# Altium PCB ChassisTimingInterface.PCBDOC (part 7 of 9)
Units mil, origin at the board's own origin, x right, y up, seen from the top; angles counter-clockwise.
Board outline 7007.87 x 4368.85 mil, 10 copper layers (Top Layer, Int1 (GND), Int2 (Sign), Int3 (Sign), Int4 (PWR), Int5 (GND), Int6 (Sign), Int7 (Sign), Int8 (GND), Bottom Layer), stack 54.89 mil thick; 537 components, 525 nets, 2288 pads, 1306 vias.
Unrouted connection lines stored in the file: 373.
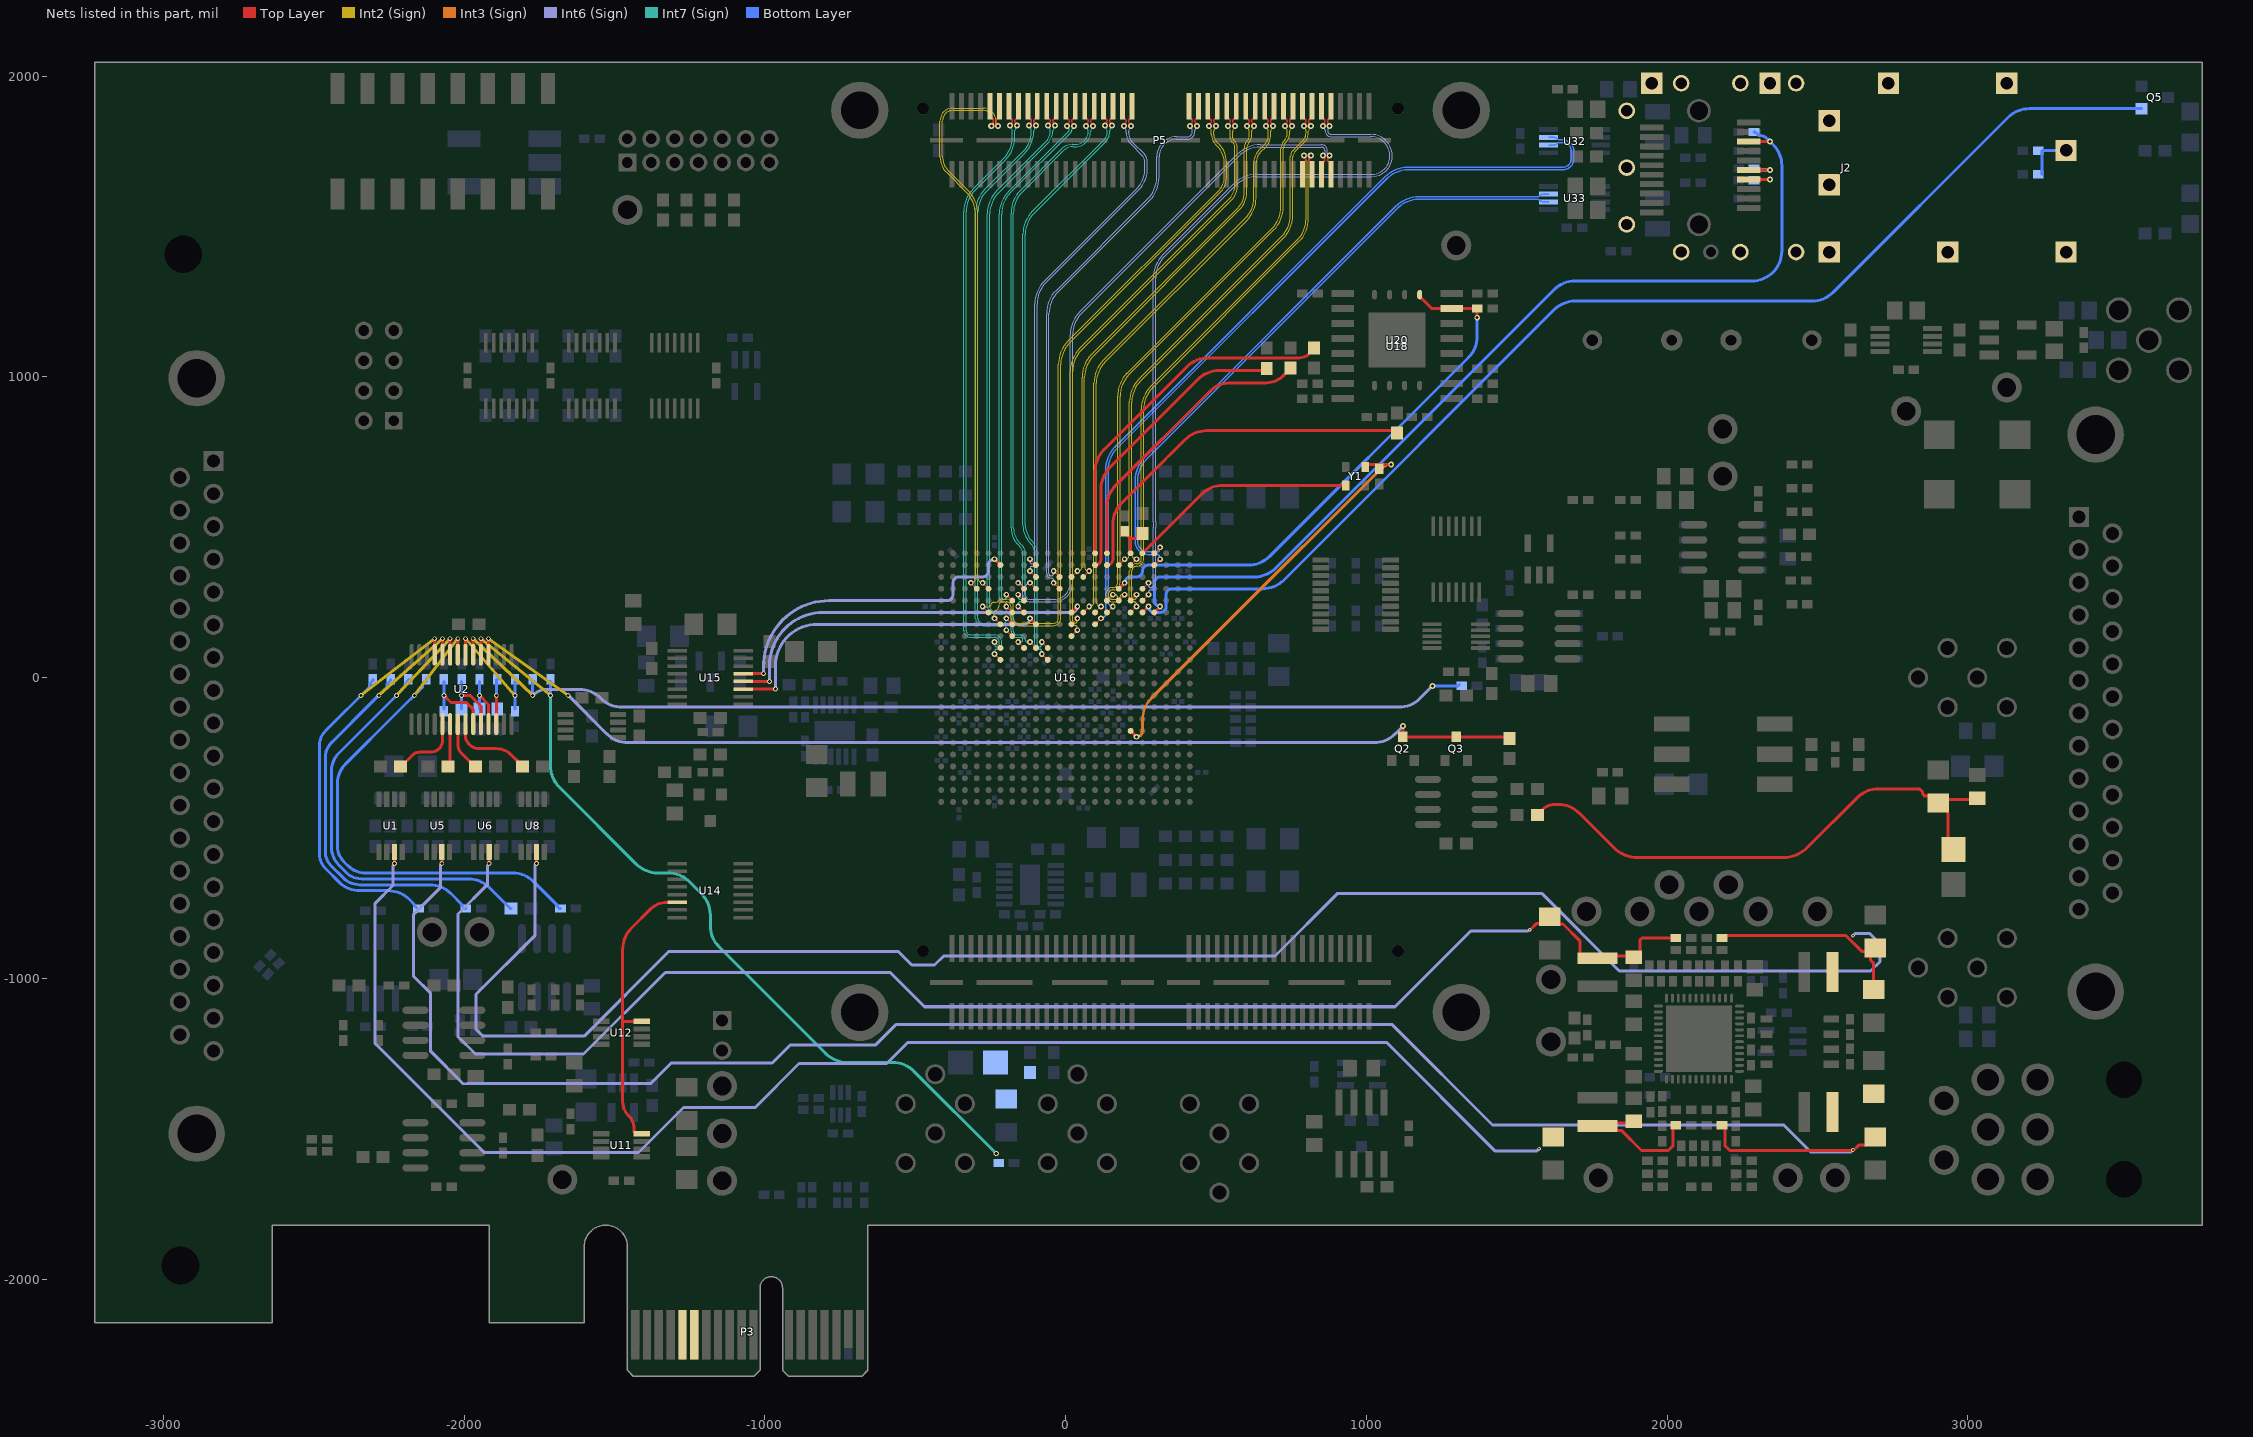
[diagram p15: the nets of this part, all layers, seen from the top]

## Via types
v1: diameter 19, hole 10, Top Layer to Bottom Layer, tented both sides, 667 vias
v2: diameter 20, hole 10, Top Layer to Bottom Layer, tented both sides, 248 vias
v3: diameter 16, hole 10, Top Layer to Bottom Layer, tented both sides, 191 vias
v4: diameter 12, hole 6, Top Layer to Bottom Layer, tented both sides, 85 vias
v5: diameter 19.68, hole 10, Top Layer to Bottom Layer, tented both sides, 50 vias
v6: diameter 17.72, hole 10, Top Layer to Bottom Layer, tented both sides, 19 vias
v7: diameter 19, hole 10, Top Layer to Bottom Layer, 15 vias
v8: diameter 23.62, hole 10, Top Layer to Bottom Layer, tented both sides, 14 vias
v9: diameter 20, hole 10, Top Layer to Bottom Layer, 11 vias
v10: diameter 16, hole 10, Top Layer to Bottom Layer, 3 vias
v11: diameter 22, hole 12, Top Layer to Bottom Layer, tented both sides, 2 vias
v12: diameter 19.02, hole 10, Top Layer to Bottom Layer, tented both sides, 1 vias

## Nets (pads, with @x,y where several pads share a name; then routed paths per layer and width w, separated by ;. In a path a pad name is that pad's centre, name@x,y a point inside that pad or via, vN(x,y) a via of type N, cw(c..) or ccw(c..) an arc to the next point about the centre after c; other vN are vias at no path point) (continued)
S33_48.S47_N: P5.67 U16.U18 | length 1841.6
  Top Layer w5: U16.U18@216.54,255.91 v1(236.22,275.59) ; v2(815.43,1736.22) cw(c807.53,1736.22) 813.12,1730.63 810.97,1728.48 ccw(c817.59,1721.87) 808.23,1721.87 ccw(c815.64,1721.87) 810.4,1716.63 ccw(c812.94,1719.18) 812.94,1715.58 cw(c812.94,1711.99) 815.48,1714.53 817.06,1712.95 cw(c810.72,1706.62) 819.68,1706.62 P5.67@819.68,1673.83
  Int2 (Sign) w3: v1(236.22,275.59) 236.22,267.78 cw(c228.35,267.78) 228.35,259.91 cw(c228.35,267.78) 220.47,267.78 220.47,354.33 cw(c236.22,354.33) 236.22,370.08 236.35,370.08 ccw(c236.35,393.7) 259.97,393.7 259.97,892.27 cw(c359.97,892.27) 289.13,962.86 cw(c359.97,892.27) 289.26,962.98 776.33,1450.05 ccw(c700.03,1526.35) 807.93,1526.35 807.93,1718.11 cw(c826.88,1718.11) 813.48,1731.51 ccw(c808.77,1736.22) v2(815.43,1736.22)
S33_48.S47_P: P5.65 U16.U17 | length 1854.2
  Top Layer w5: U16.U17@216.54,216.54 v1(236.22,236.22) ; P5.65@788.18,1673.83 788.18,1706.62 cw(c797.14,1706.62) 790.81,1712.96 792.38,1714.53 cw(c794.92,1711.99) 794.92,1715.58 ccw(c794.92,1719.18) 797.46,1716.63 ccw(c792.23,1721.87) 799.63,1721.87 ccw(c790.27,1721.87) 796.9,1728.48 794.74,1730.64 cw(c800.33,1736.22) v2(792.43,1736.22)
  Int2 (Sign) w3: v1(236.22,236.22) 236.22,244.03 ccw(c228.35,244.03) 228.35,251.91 cw(c228.35,267.78) 212.47,267.78 212.47,354.33 cw(c236.22,354.33) 236.22,378.08 236.35,378.08 ccw(c236.35,393.7) 251.97,393.7 251.97,893 cw(c358.22,893) 283.09,968.13 770.64,1455.68 ccw(c699.93,1526.39) 799.93,1526.39 799.93,1718.11 ccw(c780.98,1718.11) 794.38,1731.51 cw(c799.09,1736.22) v2(792.43,1736.22)
S33_48.S48_N: P5.69 U16.H19 | length 2326.4
  Top Layer w5: v1(-157.48,314.96) U16.H19@-137.8,295.28 ; P5.69@851.16,1673.83 851.16,1706.62 cw(c860.13,1706.62) 853.79,1712.96 855.37,1714.53 cw(c857.9,1711.99) 857.9,1715.58 ccw(c857.9,1719.18) 860.45,1716.63 ccw(c855.21,1721.87) 862.61,1721.87 ccw(c853.25,1721.87) 859.88,1728.48 857.72,1730.64 cw(c863.31,1736.22) v2(855.41,1736.22)
  Int6 (Sign) w3: v1(-157.48,314.96) cw(c-157.48,299.28) -141.8,299.28 -141.8,275.53 ccw(c-118.11,275.53) -118.11,251.84 -39.37,251.84 ccw(c-39.37,314.96) 23.75,314.96 23.75,1139.81 cw(c123.75,1139.81) 53.04,1210.52 577.01,1734.49 cw(c647.72,1663.78) 647.72,1763.78 851.1,1763.78 cw(c851.1,1751.97) 862.91,1751.97 862.91,1743.72 cw(c855.41,1743.72) v2(855.41,1736.22)
S33_48.S48_P: P5.71 U16.J19 | length 2326.4
  Top Layer w5: v1(-118.11,314.96) U16.J19@-98.43,295.28 ; v2(878.41,1736.22) cw(c870.52,1736.22) 876.1,1730.63 873.95,1728.48 ccw(c880.58,1721.87) 871.21,1721.87 ccw(c878.62,1721.87) 873.38,1716.63 ccw(c875.93,1719.18) 875.93,1715.58 cw(c875.93,1711.99) 878.46,1714.53 880.05,1712.95 cw(c873.7,1706.62) 882.66,1706.62 P5.71@882.66,1673.83
  Int6 (Sign) w3: v1(-118.11,314.96) ccw(c-118.11,299.28) -133.8,299.28 -133.8,275.53 ccw(c-118.11,275.53) -118.11,259.84 -39.37,259.84 ccw(c-39.37,314.96) 15.75,314.96 15.75,1139.85 cw(c123.65,1139.85) 47.35,1216.15 571.38,1740.18 cw(c647.68,1663.88) 647.68,1771.78 851.1,1771.78 cw(c851.1,1751.97) 870.91,1751.97 870.91,1743.72 ccw(c878.41,1743.72) v2(878.41,1736.22)
S49_64.S49_N: P5.12 U16.D19 | length 1942
  Top Layer w5: v1(-314.96,314.96) U16.D19@-295.28,295.28 ; v2(-223.92,1834.65) ccw(c-231.82,1834.65) -226.22,1840.22 -227.52,1841.52 cw(c-218.83,1850.21) -231.12,1850.21 -231.12,1851.36 cw(c-223.71,1851.36) -228.95,1856.59 cw(c-226.41,1854.05) -226.41,1857.65 ccw(c-226.41,1861.24) -223.87,1858.69 -222.29,1860.27 ccw(c-228.63,1866.61) -219.67,1866.61 P5.12@-219.67,1899.4
  Int2 (Sign) w3: v1(-314.96,314.96) ccw(c-314.96,330.65) -299.28,330.65 -299.28,1541.82 ccw(c-399.28,1541.82) -328.57,1612.53 -395.65,1679.61 cw(c-343.01,1732.24) -417.45,1732.24 -417.45,1850.39 cw(c-374.02,1850.39) -374.02,1893.83 -274.06,1893.83 cw(c-274.06,1851.18) -231.42,1851.18 -231.42,1842.15 ccw(c-223.92,1842.15) v2(-223.92,1834.65)
S49_64.S49_P: P5.10 U16.E19 | length 1916.9
  Top Layer w5: v1(-275.59,314.96) U16.E19@-255.91,295.28 ; P5.10@-251.17,1899.4 -251.17,1866.61 ccw(c-242.21,1866.61) -248.55,1860.28 -246.97,1858.7 ccw(c-244.43,1861.24) -244.43,1857.65 cw(c-244.43,1854.05) -241.89,1856.59 cw(c-247.12,1851.36) -239.72,1851.36 -239.72,1850.21 cw(c-252.01,1850.21) -243.32,1841.52 -244.6,1840.23 ccw(c-239.02,1834.65) v2(-246.92,1834.65)
  Int2 (Sign) w3: v1(-275.59,314.96) cw(c-275.59,330.65) -291.28,330.65 -291.28,1541.92 ccw(c-399.04,1541.92) -322.84,1618.11 -389.96,1685.24 cw(c-342.92,1732.28) -409.45,1732.28 -409.45,1850.39 cw(c-374.02,1850.39) -374.02,1885.83 -274.06,1885.83 cw(c-274.06,1851.18) -239.42,1851.18 -239.42,1842.15 cw(c-246.92,1842.15) v2(-246.92,1834.65)
S49_64.S50_N: P5.14 U16.F14 | length 2018.6
  Top Layer w5: v1(-236.22,118.11) U16.F14@-216.54,98.43 ; P5.14@-188.19,1899.4 -188.19,1866.61 ccw(c-179.22,1866.61) -185.57,1860.28 -183.99,1858.7 ccw(c-181.45,1861.24) -181.45,1857.65 cw(c-181.45,1854.05) -178.9,1856.59 cw(c-184.14,1851.36) -176.74,1851.36 cw(c-189.01,1851.36) -180.33,1842.68 -181.62,1841.39 ccw(c-176.04,1835.8) v2(-183.94,1835.8)
  Int7 (Sign) w3: v1(-236.22,118.11) -236.22,110.3 ccw(c-228.35,110.3) -228.35,102.43 ccw(c-228.35,110.3) -220.47,110.3 -220.47,118.11 ccw(c-236.22,118.11) -236.22,133.86 -314.96,133.86 cw(c-314.96,157.61) -338.71,157.61 -338.71,196.98 -338.71,1548.37 cw(c-230.81,1548.37) -307.11,1624.67 -205.72,1726.05 ccw(c-276.44,1796.76) -176.44,1796.76 -176.44,1817.7 ccw(c-195.38,1817.7) -181.99,1831.09 cw(c-177.28,1835.8) v2(-183.94,1835.8)
S49_64.S50_P: P5.16 U16.F13 | length 2031.2
  Top Layer w5: v1(-236.22,78.74) U16.F13@-216.54,59.06 ; v2(-160.94,1835.8) ccw(c-168.83,1835.8) -163.24,1841.38 -164.54,1842.68 cw(c-155.86,1851.36) -168.14,1851.36 cw(c-160.73,1851.36) -165.97,1856.59 cw(c-163.42,1854.05) -163.42,1857.65 ccw(c-163.42,1861.24) -160.89,1858.69 -159.31,1860.27 ccw(c-165.65,1866.61) -156.68,1866.61 P5.16@-156.69,1899.4
  Int7 (Sign) w3: v1(-236.22,78.74) -236.22,86.55 cw(c-228.35,86.55) -228.35,94.43 ccw(c-228.35,110.3) -212.47,110.3 -212.47,118.11 ccw(c-236.22,118.11) -236.22,141.86 -314.96,141.86 cw(c-314.96,157.61) -330.71,157.61 -330.71,1460.63 -330.71,1548.33 cw(c-230.71,1548.33) -301.42,1619.04 -200.04,1720.42 ccw(c-276.34,1796.72) -168.44,1796.72 -168.44,1817.7 cw(c-149.49,1817.7) -162.88,1831.09 ccw(c-167.59,1835.8) v2(-160.94,1835.8)
S49_64.S51_N: P5.20 U16.G16 | length 1924
  Top Layer w5: v1(-196.85,196.85) U16.G16@-177.17,177.17 ; v2(-97.94,1834.95) ccw(c-105.83,1834.95) -100.24,1840.53 -101.54,1841.82 cw(c-92.84,1850.51) -105.14,1850.51 -105.14,1851.36 cw(c-97.73,1851.36) -102.97,1856.59 cw(c-100.42,1854.05) -100.42,1857.65 ccw(c-100.42,1861.24) -97.89,1858.69 -96.31,1860.27 ccw(c-102.65,1866.61) -93.68,1866.61 P5.20@-93.69,1899.4
  Int7 (Sign) w3: v1(-196.85,196.85) -196.85,189.04 cw(c-204.72,189.04) -204.72,181.17 -275.59,181.17 cw(c-275.59,196.91) -291.34,196.91 -291.34,1546.82 cw(c-191.34,1546.82) -262.05,1617.53 -135.52,1744.06 ccw(c-208.15,1816.69) -105.44,1816.69 -105.44,1816.84 cw(c-86.49,1816.84) -99.88,1830.24 ccw(c-104.59,1834.95) v2(-97.94,1834.95)
S49_64.S51_P: P5.18 U16.G15 | length 1936.5
  Top Layer w5: v1(-196.85,157.48) U16.G15@-177.17,137.8 ; P5.18@-125.19,1899.4 -125.19,1866.61 ccw(c-116.22,1866.61) -122.57,1860.28 -120.99,1858.7 ccw(c-118.45,1861.24) -118.45,1857.65 cw(c-118.45,1854.05) -115.9,1856.59 cw(c-121.14,1851.36) -113.74,1851.36 -113.74,1850.51 cw(c-126.03,1850.51) -117.34,1841.82 -118.62,1840.53 ccw(c-113.04,1834.95) v2(-120.94,1834.95)
  Int7 (Sign) w3: v1(-196.85,157.48) -196.85,165.29 ccw(c-204.72,165.29) -204.72,173.17 -275.59,173.17 cw(c-275.59,196.91) -299.34,196.91 -299.34,1546.86 cw(c-191.44,1546.86) -267.74,1623.16 -141.29,1749.6 ccw(c-208.52,1816.84) -113.44,1816.84 ccw(c-132.38,1816.84) -118.99,1830.24 cw(c-114.28,1834.95) v2(-120.94,1834.95)
S49_64.S52_N: P5.22 U16.H14 | length 2000.4
  Top Layer w5: v1(-157.48,118.11) U16.H14@-137.8,98.43 ; P5.22@-62.2,1899.4 -62.2,1866.61 ccw(c-53.24,1866.61) -59.58,1860.28 -58,1858.7 ccw(c-55.46,1861.24) -55.46,1857.65 cw(c-55.46,1854.05) -52.92,1856.59 cw(c-58.16,1851.36) -50.75,1851.36 -50.75,1850.51 cw(c-63.04,1850.51) -54.35,1841.82 -55.64,1840.53 ccw(c-50.05,1834.95) v2(-57.95,1834.95)
  Int7 (Sign) w3: v1(-157.48,118.11) -149.67,118.11 ccw(c-149.67,125.98) -141.8,125.98 ccw(c-149.67,125.98) -149.67,133.86 -161.42,133.86 cw(c-161.42,153.67) -181.23,153.67 -181.23,196.98 ccw(c-196.85,196.98) -196.85,212.6 -236.22,212.6 cw(c-236.22,236.35) -259.97,236.35 -259.97,1542.18 cw(c-152.07,1542.18) -228.37,1618.48 -64.91,1781.93 ccw(c-99.82,1816.84) -50.45,1816.84 ccw(c-69.4,1816.84) -56,1830.24 cw(c-51.29,1834.95) v2(-57.95,1834.95)
S49_64.S52_P: P5.24 U16.J14 | length 2000.5
  Top Layer w5: v1(-118.11,118.11) U16.J14@-98.43,98.43 ; v2(-34.95,1834.95) ccw(c-42.85,1834.95) -37.26,1840.53 -38.55,1841.82 cw(c-29.86,1850.51) -42.15,1850.51 -42.15,1851.36 cw(c-34.75,1851.36) -39.98,1856.59 cw(c-37.44,1854.05) -37.44,1857.65 ccw(c-37.44,1861.24) -34.91,1858.69 -33.33,1860.27 ccw(c-39.66,1866.61) -30.7,1866.61 P5.24@-30.7,1899.4
  Int7 (Sign) w3: v1(-118.11,118.11) -125.92,118.11 cw(c-125.92,125.98) -133.8,125.98 ccw(c-149.67,125.98) -149.67,141.86 -161.42,141.86 cw(c-161.42,153.67) -173.23,153.67 -173.23,196.98 ccw(c-196.85,196.98) -196.85,220.6 -236.22,220.6 cw(c-236.22,236.35) -251.97,236.35 -251.97,1542.14 cw(c-151.97,1542.14) -222.68,1612.85 -59.25,1776.28 ccw(c-99.8,1816.83) -42.45,1816.83 cw(c-23.5,1816.84) -36.9,1830.24 ccw(c-41.61,1834.95) v2(-34.95,1834.95)
S49_64.S53_N: P5.28 U16.G18 | length 1793.8
  Top Layer w5: v1(-196.85,275.59) U16.G18@-177.17,255.91 ; v2(28.05,1834.65) ccw(c20.15,1834.65) 25.74,1840.22 24.45,1841.52 cw(c33.14,1850.21) 20.85,1850.21 20.85,1851.36 cw(c28.25,1851.36) 23.02,1856.59 cw(c25.56,1854.05) 25.56,1857.65 ccw(c25.56,1861.24) 28.09,1858.69 29.67,1860.27 ccw(c23.34,1866.61) 32.3,1866.61 P5.28@32.3,1899.4
  Int7 (Sign) w3: v1(-196.85,275.59) -196.85,267.78 cw(c-204.72,267.78) -204.72,259.91 cw(c-204.72,267.78) -212.6,267.78 -212.6,1540.98 cw(c-112.6,1540.98) -183.31,1611.69 17.42,1812.42 ccw(c9.87,1819.97) 20.55,1819.97 cw(c31.22,1819.97) 23.67,1827.52 26.1,1829.94 ccw(c21.39,1834.65) v2(28.05,1834.65)
S49_64.S53_P: P5.26 U16.G17 | length 1806.3
  Top Layer w5: v1(-196.85,236.22) U16.G17@-177.17,216.54 ; P5.26@0.8,1899.4 0.8,1866.61 ccw(c9.76,1866.61) 3.42,1860.28 5,1858.7 ccw(c7.54,1861.24) 7.54,1857.65 cw(c7.54,1854.05) 10.08,1856.59 cw(c4.84,1851.36) 12.25,1851.36 12.25,1850.21 cw(c-0.04,1850.21) 8.65,1841.52 7.36,1840.23 ccw(c12.95,1834.65) v2(5.05,1834.65)
  Int7 (Sign) w3: v1(-196.85,236.22) -196.85,244.03 ccw(c-204.72,244.03) -204.72,251.91 cw(c-204.72,267.78) -220.6,267.78 -220.6,1541.02 cw(c-112.7,1541.02) -189,1617.31 10.59,1816.9 ccw(c5.87,1821.62) 12.55,1821.62 ccw(c5.87,1821.62) 10.59,1826.34 7,1829.94 cw(c11.71,1834.65) v2(5.05,1834.65)
S49_64.S54_N: P5.30 U16.H18 | length 1836.4
  Top Layer w5: v1(-157.48,275.59) U16.H18@-137.8,255.91 ; P5.30@63.78,1899.4 63.78,1866.61 ccw(c72.74,1866.61) 66.4,1860.28 67.98,1858.7 ccw(c70.52,1861.24) 70.52,1857.65 cw(c70.52,1854.05) 73.06,1856.59 cw(c67.83,1851.36) 75.23,1851.36 75.23,1850.21 cw(c62.94,1850.21) 71.63,1841.52 70.35,1840.23 ccw(c75.93,1834.65) v2(68.03,1834.65)
  Int7 (Sign) w3: v1(-157.48,275.59) -157.48,267.78 ccw(c-149.67,267.75) -141.86,267.78 -141.86,413.28 ccw(c-170.93,413.28) -150.37,433.84 -157.52,440.99 cw(c-100.3,498.21) -181.23,498.21 -181.23,1543.73 cw(c-73.33,1543.73) -149.62,1620.03 -10.03,1759.63 cw(c22.3,1727.31) 22.3,1773.02 32.01,1773.02 ccw(c32.01,1816.54) 75.53,1816.54 ccw(c56.58,1816.54) 69.98,1829.94 cw(c74.69,1834.65) v2(68.03,1834.65)
S49_64.S54_P: P5.32 U16.H17 | length 1848.7
  Top Layer w5: v1(-157.48,236.22) U16.H17@-137.8,216.54 ; v2(91.03,1834.65) ccw(c83.13,1834.65) 88.73,1840.22 87.43,1841.52 cw(c96.12,1850.21) 83.83,1850.21 83.83,1851.36 cw(c91.24,1851.36) 86,1856.59 cw(c88.54,1854.05) 88.54,1857.65 ccw(c88.54,1861.24) 91.08,1858.69 92.66,1860.27 ccw(c86.32,1866.61) 95.28,1866.61 P5.32@95.28,1899.4
  Int7 (Sign) w3: v1(-157.48,236.22) -157.48,244.03 cw(c-149.61,244.03) -149.61,251.91 ccw(c-149.61,267.65) -133.86,267.65 -133.86,413.39 ccw(c-170.68,413.39) -144.64,439.42 -151.82,446.6 cw(c-100.15,498.28) -173.23,498.28 -173.23,1543.69 cw(c-73.23,1543.69) -143.94,1614.4 -6.71,1751.63 cw(c25.61,1719.31) 25.61,1765.02 32.01,1765.02 ccw(c32.01,1816.54) 83.53,1816.5 ; 83.53,1816.54 cw(c102.48,1816.54) 89.08,1829.94 ccw(c84.37,1834.65) v2(91.03,1834.65)
S49_64.S55_N: P5.36 U16.K14 | length 1980
  Top Layer w5: v1(-78.74,118.11) U16.K14@-59.06,98.43 ; v2(154.03,1834.95) ccw(c146.13,1834.95) 151.73,1840.53 150.43,1841.82 cw(c159.12,1850.51) 146.83,1850.51 146.83,1851.36 cw(c154.24,1851.36) 149,1856.59 cw(c151.54,1854.05) 151.54,1857.65 ccw(c151.54,1861.24) 154.08,1858.69 155.66,1860.27 ccw(c149.32,1866.61) 158.28,1866.61 P5.36@158.28,1899.4
  Int7 (Sign) w3: v1(-78.74,118.11) -78.74,110.3 cw(c-86.61,110.3) -86.61,102.43 cw(c-86.61,110.3) -94.49,110.3 -94.49,413.48 ccw(c-150.08,413.48) -110.77,452.79 cw(c-55.03,508.53) -133.86,508.53 -133.86,1473.77 cw(c-33.86,1473.77) -104.57,1544.48 136.32,1785.37 ccw(c111.67,1810.02) 146.53,1810.02 146.53,1816.84 cw(c165.48,1816.84) 152.08,1830.24 ccw(c147.37,1834.95) v2(154.03,1834.95)
S49_64.S55_P: P5.34 U16.K13 | length 1992.7
  Top Layer w5: v1(-78.74,78.74) U16.K13@-59.06,59.06 ; P5.34@126.78,1899.4 126.78,1866.61 ccw(c135.74,1866.61) 129.4,1860.28 130.98,1858.7 ccw(c133.52,1861.24) 133.52,1857.65 cw(c133.52,1854.05) 136.06,1856.59 cw(c130.83,1851.36) 138.23,1851.36 138.23,1850.51 cw(c125.94,1850.51) 134.63,1841.82 133.35,1840.53 ccw(c138.93,1834.95) v2(131.03,1834.95)
  Int7 (Sign) w3: v1(-78.74,78.74) -78.74,86.55 ccw(c-86.61,86.55) -86.61,94.43 cw(c-86.61,110.3) -102.49,110.3 -102.49,413.39 ccw(c-150.32,413.39) -116.5,447.21 -118.11,448.82 cw(c-60.78,506.15) -141.86,506.15 -141.86,1473.81 cw(c-33.96,1473.81) -110.25,1550.11 129.95,1790.32 ccw(c109.25,1811.02) 138.53,1811.02 138.53,1816.84 ccw(c119.58,1816.84) 132.98,1830.24 cw(c137.69,1834.95) v2(131.03,1834.95)
S49_64.S56_N: P5.38 U16.J21 | length 1749.2
  Top Layer w5: v1(-118.11,393.7) U16.J21@-98.43,374.02 ; P5.38@189.76,1899.4 189.76,1866.61 ccw(c198.73,1866.61) 192.38,1860.28 193.96,1858.7 ccw(c196.5,1861.24) 196.5,1857.65 cw(c196.5,1854.05) 199.05,1856.59 cw(c193.81,1851.36) 201.21,1851.36 201.21,1850.21 cw(c188.92,1850.21) 197.61,1841.52 196.33,1840.23 ccw(c201.91,1834.65) v2(194.01,1834.65)
  Int6 (Sign) w3: v1(-118.11,393.7) -118.11,385.89 ccw(c-110.24,385.89) -110.24,378.02 ccw(c-110.24,385.89) -102.36,385.89 -102.36,1242.21 cw(c5.54,1242.21) -70.79,1318.47 ; -70.76,1318.51 238.37,1627.64 ccw(c177.04,1688.98) 263.78,1688.98 263.78,1716.54 ccw(c237.11,1716.54) 255.97,1735.39 216.88,1774.48 cw(c253.97,1811.57) 201.51,1811.57 201.51,1816.54 ccw(c182.57,1816.54) 195.96,1829.94 cw(c200.67,1834.65) v2(194.01,1834.65)
S49_64.S56_P: P5.40 U16.J20 | length 1761.8
  Top Layer w5: v1(-118.11,354.33) U16.J20@-98.43,334.65 ; v2(217.01,1834.65) ccw(c209.12,1834.65) 214.71,1840.22 213.41,1841.52 cw(c222.11,1850.21) 209.81,1850.21 209.81,1851.36 cw(c217.22,1851.36) 211.98,1856.59 cw(c214.53,1854.05) 214.53,1857.65 ccw(c214.53,1861.24) 217.06,1858.69 218.64,1860.27 ccw(c212.3,1866.61) 221.27,1866.61 P5.40@221.26,1899.4
  Int6 (Sign) w3: v1(-118.11,354.33) -118.11,362.14 cw(c-110.24,362.14) -110.24,370.02 ccw(c-110.24,385.89) -94.36,385.89 -94.36,1242.17 cw(c5.64,1242.17) -65.07,1312.88 244.13,1622.09 ccw(c177.39,1688.83) 271.78,1688.83 271.78,1716.6 ccw(c237.28,1716.6) 261.67,1741 224.26,1778.42 ; v2(217.01,1834.65) cw(c210.36,1834.65) 215.07,1829.94 ccw(c228.46,1816.54) 209.52,1816.54 209.51,1811.61 ccw(c254.05,1811.61) 222.56,1780.12 224.24,1778.44
S49_64.S57_N: P5.44 U16.L20 | length 1848.9
  Top Layer w5: v1(-39.37,354.33) U16.L20@-19.69,334.65 ; v2(437.48,1834.65) ccw(c429.58,1834.65) 435.18,1840.22 433.88,1841.52 cw(c442.57,1850.21) 430.28,1850.21 430.28,1851.36 cw(c437.69,1851.36) 432.45,1856.59 cw(c434.99,1854.05) 434.99,1857.65 ccw(c434.99,1861.24) 437.53,1858.69 439.11,1860.27 ccw(c432.77,1866.61) 441.73,1866.61 P5.44@441.73,1899.4
  Int6 (Sign) w3: v1(-39.37,354.33) -39.37,346.52 cw(c-47.24,346.52) -47.24,338.65 cw(c-47.24,346.52) -55.12,346.52 -55.12,1210.55 cw(c44.88,1210.55) -25.83,1281.26 279.44,1586.53 ccw(c203.14,1662.82) 311.04,1662.82 311.04,1731.24 cw(c370.08,1731.24) 370.08,1790.28 405.3,1790.28 ccw(c405.3,1814.96) 429.98,1814.96 429.98,1818.9 cw(c443.24,1818.9) 433.86,1828.26 435.53,1829.94 ccw(c430.82,1834.65) v2(437.48,1834.65)
S49_64.S57_P: P5.42 U16.L19 | length 1861.4
  Top Layer w5: v1(-39.37,314.96) U16.L19@-19.69,295.28 ; P5.42@410.23,1899.4 410.23,1866.61 ccw(c419.19,1866.61) 412.85,1860.28 414.43,1858.7 ccw(c416.97,1861.24) 416.97,1857.65 cw(c416.97,1854.05) 419.51,1856.59 cw(c414.28,1851.36) 421.68,1851.36 421.68,1850.21 cw(c409.39,1850.21) 418.08,1841.52 416.8,1840.23 ccw(c422.38,1834.65) v2(414.48,1834.65)
  Int6 (Sign) w3: v1(-39.37,314.96) -39.37,322.77 ccw(c-47.24,322.77) -47.24,330.65 cw(c-47.24,346.52) -63.12,346.52 -63.12,1210.59 cw(c44.78,1210.59) -31.55,1286.85 ; -31.51,1286.89 273.75,1592.15 ccw(c203.04,1662.86) 303.04,1662.86 303.04,1731.24 cw(c370.08,1731.24) 370.08,1798.28 405.3,1798.28 ccw(c405.3,1814.96) 421.98,1814.96 421.98,1818.9 ccw(c408.73,1818.9) 418.11,1828.26 416.42,1829.95 cw(c421.14,1834.65) v2(414.48,1834.65)
S49_64.S58_N: P5.46 U16.E17 | length 2306
  Top Layer w5: v1(-275.59,236.22) U16.E17@-255.91,216.54 ; P5.46@473.21,1899.4 473.21,1866.61 ccw(c482.18,1866.61) 475.83,1860.28 477.41,1858.7 ccw(c479.95,1861.24) 479.95,1857.65 cw(c479.95,1854.05) 482.5,1856.59 cw(c477.26,1851.36) 484.66,1851.36 484.66,1850.21 cw(c472.37,1850.21) 481.06,1841.52 479.78,1840.23 ccw(c485.36,1834.65) v2(477.46,1834.65)
  Int2 (Sign) w3: v1(-275.59,236.22) -252.95,236.22 ccw(c-252.95,239.22) -250,238.69 cw(c-236.22,236.22) -236.22,250.22 ccw(c-236.22,270.44) -221.92,256.14 cw(c-212.68,246.91) -212.68,259.97 -196.85,259.97 cw(c-196.85,236.35) -173.23,236.35 -173.23,196.85 ccw(c-157.48,196.85) -157.48,181.1 -39.37,181.1 ccw(c-39.37,196.85) -23.62,196.85 -23.62,1041.92 cw(c84.28,1041.92) 7.98,1118.22 510.86,1621.09 ccw(c470.53,1661.42) 527.56,1661.31 ccw(c470.53,1661.42) 527.56,1661.42 527.56,1712.6 ccw(c450.32,1712.6) 504.94,1767.21 498.47,1773.69 cw(c531.06,1806.28) 484.96,1806.28 484.96,1816.54 ccw(c466.02,1816.54) 479.41,1829.94 cw(c484.12,1834.65) v2(477.46,1834.65)
S49_64.S58_P: P5.48 U16.F16 | length 2312.3
  Top Layer w5: v1@-236.13,196.94 -216.54,177.35 U16.F16@-216.54,177.17 ; v2(500.46,1834.65) ccw(c492.57,1834.65) 498.16,1840.22 496.86,1841.52 cw(c505.56,1850.21) 493.26,1850.21 493.26,1851.36 cw(c500.67,1851.36) 495.43,1856.59 cw(c497.98,1854.05) 497.98,1857.65 ccw(c497.98,1861.24) 500.51,1858.69 502.09,1860.27 ccw(c495.75,1866.61) 504.72,1866.61 P5.48@504.71,1899.4
  Int2 (Sign) w3: v1(-236.22,196.85) -236.22,219.49 cw(c-233.22,219.49) -233.77,222.44 ccw(c-236.22,236.22) -222.22,236.15 cw(c-202,236.15) -216.3,250.45 cw(c-212.63,246.78) -212.63,251.97 -196.85,251.97 cw(c-196.85,236.35) -181.23,236.35 -181.23,196.85 ccw(c-157.48,196.85) -157.48,173.1 -39.37,173.1 ccw(c-39.37,196.85) -15.62,196.85 -15.62,1041.88 cw(c84.38,1041.88) 13.67,1112.59 516.62,1615.55 ccw(c470.91,1661.26) 535.56,1661.26 535.56,1712.71 ccw(c450.59,1712.71) 510.67,1772.79 504.42,1779.05 cw(c532.07,1806.7) 492.96,1806.7 492.96,1816.54 cw(c511.91,1816.54) 498.52,1829.94 ccw(c493.81,1834.65) v2(500.46,1834.65)
S49_64.S59_N: P5.52 U16.M16 | length 2004.5
  Top Layer w5: U16.M16@19.69,177.17 v1(39.37,196.85) ; v2(563.46,1834.65) ccw(c555.57,1834.65) 561.16,1840.22 559.86,1841.52 cw(c568.56,1850.21) 556.26,1850.21 556.26,1851.36 cw(c563.67,1851.36) 558.43,1856.59 cw(c560.98,1854.05) 560.98,1857.65 ccw(c560.98,1861.24) 563.51,1858.69 565.09,1860.27 ccw(c558.75,1866.61) 567.72,1866.61 P5.52@567.71,1899.4
  Int2 (Sign) w3: v1(39.37,196.85) 39.37,188.76 cw(c31.77,188.76) 31.77,181.17 cw(c31.77,189.32) 23.62,189.32 23.62,1018.13 cw(c123.62,1018.13) 52.91,1088.84 551.74,1587.67 ccw(c505.56,1633.85) 570.87,1633.85 570.87,1764.16 ccw(c543.28,1764.16) 562.79,1783.67 559.06,1787.4 cw(c566.52,1794.86) 555.96,1794.86 555.96,1816.54 cw(c574.91,1816.54) 561.52,1829.94 ccw(c556.81,1834.65) v2(563.46,1834.65)
S49_64.S59_P: P5.50 U16.M15 | length 2017
  Top Layer w5: U16.M15@19.69,137.8 v1(39.37,157.48) ; P5.50@536.21,1899.4 536.21,1866.61 ccw(c545.18,1866.61) 538.83,1860.28 540.41,1858.7 ccw(c542.95,1861.24) 542.95,1857.65 cw(c542.95,1854.05) 545.5,1856.59 cw(c540.26,1851.36) 547.66,1851.36 547.66,1850.21 cw(c535.37,1850.21) 544.06,1841.52 542.78,1840.23 ccw(c548.36,1834.65) v2(540.46,1834.65)
  Int2 (Sign) w3: v1(39.37,157.48) 39.37,165.57 ccw(c31.77,165.57) 31.77,173.17 cw(c31.77,189.32) 15.62,189.32 15.62,1018.17 cw(c123.52,1018.17) 47.23,1094.47 546.07,1593.32 ccw(c505.53,1633.86) 562.87,1633.86 562.87,1764.12 ccw(c543.18,1764.12) 557.1,1778.04 553.36,1781.78 cw(c566.42,1794.82) 547.96,1794.82 547.96,1816.54 ccw(c529.02,1816.54) 542.41,1829.94 cw(c547.12,1834.65) v2(540.46,1834.65)
S49_64.S60_N: P5.54 U16.M20 | length 1812.2
  Top Layer w5: U16.M20@19.69,334.65 v1(39.37,354.33) ; P5.54@599.2,1899.4 599.2,1866.61 ccw(c608.16,1866.61) 601.82,1860.28 603.4,1858.7 ccw(c605.94,1861.24) 605.94,1857.65 cw(c605.94,1854.05) 608.48,1856.59 cw(c603.24,1851.36) 610.65,1851.36 610.65,1850.21 cw(c598.36,1850.21) 607.05,1841.52 605.76,1840.23 ccw(c611.35,1834.65) v2(603.45,1834.65)
  Int2 (Sign) w3: v1(39.37,354.33) ccw(c39.37,370.02) 55.06,370.02 55.06,936.94 54.99,937.01 54.99,998.49 cw(c162.89,998.49) 86.6,1074.78 572.22,1560.41 ccw(c518.45,1614.17) 594.49,1614.17 594.49,1760.86 cw(c628.84,1760.86) 604.55,1785.16 ; v2(603.45,1834.65) ccw(c610.11,1834.65) 605.4,1829.94 cw(c592,1816.54) 610.95,1816.54 610.95,1799.84 ; 604.58,1785.18 ccw(c589.2,1800.56) 610.95,1800.56
S49_64.S60_P: P5.56 U16.N20 | length 1811.5
  Top Layer w5: U16.N20@59.06,334.65 v1(78.74,354.33) ; v2(626.45,1834.65) ccw(c618.55,1834.65) 624.14,1840.22 622.85,1841.52 cw(c631.54,1850.21) 619.25,1850.21 619.25,1851.36 cw(c626.65,1851.36) 621.42,1856.59 cw(c623.96,1854.05) 623.96,1857.65 ccw(c623.96,1861.24) 626.49,1858.69 628.07,1860.27 ccw(c621.74,1866.61) 630.7,1866.61 P5.56@630.7,1899.4
  Int2 (Sign) w3: v1(78.74,354.33) cw(c78.74,370.02) 63.06,370.02 63.06,940.26 62.99,940.32 62.99,998.45 cw(c162.99,998.45) 92.28,1069.16 577.91,1554.79 ccw(c518.58,1614.12) 602.49,1614.12 602.49,1760.82 cw(c628.94,1760.82) 610.24,1779.53 610.29,1779.58 ccw(c589.39,1800.48) 618.95,1800.48 618.95,1816.54 cw(c637.9,1816.54) 624.5,1829.94 ccw(c619.79,1834.65) v2(626.45,1834.65)
S49_64.S61_N: P5.60 U16.P17 | length 1936.8
  Top Layer w5: U16.P17@98.43,216.54 v1(118.11,236.22) ; v2(689.45,1834.65) ccw(c681.55,1834.65) 687.14,1840.22 685.85,1841.52 cw(c694.54,1850.21) 682.25,1850.21 682.25,1851.36 cw(c689.65,1851.36) 684.42,1856.59 cw(c686.96,1854.05) 686.96,1857.65 ccw(c686.96,1861.24) 689.49,1858.69 691.07,1860.27 ccw(c684.74,1866.61) 693.7,1866.61 P5.60@693.7,1899.4
  Int2 (Sign) w3: v1(118.11,236.22) cw(c118.11,251.91) 102.43,251.91 102.43,492.06 102.36,492.13 102.36,978.76 cw(c202.36,978.76) 131.65,1049.47 603.59,1521.41 ccw(c530.53,1594.48) 633.86,1594.33 ccw(c530.53,1594.48) 633.86,1594.48 633.86,1712.6 cw(c682.58,1712.6) 648.13,1747.05 668.32,1767.24 ccw(c635.41,1800.15) 681.95,1800.15 681.95,1816.54 cw(c700.9,1816.54) 687.5,1829.94 ccw(c682.79,1834.65) v2(689.45,1834.65)
S49_64.S61_P: P5.58 U16.N17 | length 1938.8
  Top Layer w5: U16.N17@59.06,216.54 v1(78.74,236.22) ; P5.58@662.2,1899.4 662.2,1866.61 ccw(c671.16,1866.61) 664.82,1860.28 666.4,1858.7 ccw(c668.94,1861.24) 668.94,1857.65 cw(c668.94,1854.05) 671.48,1856.59 cw(c666.24,1851.36) 673.65,1851.36 673.65,1850.21 cw(c661.36,1850.21) 670.05,1841.52 668.76,1840.23 ccw(c674.35,1834.65) v2(666.45,1834.65)
  Int2 (Sign) w3: v1(78.74,236.22) ccw(c78.74,251.91) 94.43,251.91 94.43,490.92 ; 94.43,490.97 ccw(c91.43,490.94) 94.41,491.26 cw(c102.36,492.13) 94.36,492.13 94.36,978.8 cw(c202.26,978.8) 125.97,1055.1 597.93,1527.06 ccw(c530.51,1594.49) 625.86,1594.49 ; 625.86,1592.48 625.86,1712.64 cw(c682.48,1712.64) 642.44,1752.68 662.65,1772.89 ccw(c635.41,1800.15) 673.95,1800.15 673.95,1816.54 ccw(c655,1816.54) 668.4,1829.94 cw(c673.11,1834.65) v2(666.45,1834.65)
S49_64.S62_N: P5.62 U16.T18 | length 1995.7
  Top Layer w5: U16.T18@177.17,255.91 v1(196.85,275.59) ; P5.62@725.18,1899.4 725.18,1866.61 ccw(c734.14,1866.61) 727.8,1860.28 729.38,1858.7 ccw(c731.92,1861.24) 731.92,1857.65 cw(c731.92,1854.05) 734.46,1856.59 cw(c729.23,1851.36) 736.63,1851.36 736.63,1850.21 cw(c724.34,1850.21) 733.03,1841.52 731.75,1840.23 ccw(c737.33,1834.65) v2(729.43,1834.65)
  Int2 (Sign) w3: v1(196.85,275.59) 189.04,275.59 ccw(c189.04,267.72) 181.17,267.72 cw(c165.29,267.72) 165.29,251.84 157.48,251.84 cw(c157.48,275.59) 133.73,275.59 cw(c157.48,275.59) 157.48,299.34 157.61,299.34 ccw(c157.61,314.96) 173.23,314.96 173.23,935.62 cw(c281.13,935.62) 204.35,1011.43 cw(c281.13,935.62) 204.8,1011.88 ; 204.83,1011.92 687.12,1494.21 ccw(c616.41,1564.92) 716.41,1564.92 716.41,1758.7 cw(c756.87,1758.7) 728.26,1787.32 729.08,1788.14 ccw(c710.13,1807.09) 736.93,1807.09 736.93,1816.54 ccw(c717.98,1816.54) 731.38,1829.94 cw(c736.09,1834.65) v2(729.43,1834.65)
S49_64.S62_P: P5.64 U16.R18 | length 1970.6
  Top Layer w5: U16.R18@137.8,255.91 v1(157.48,275.59) ; v2(752.43,1834.65) ccw(c744.53,1834.65) 750.13,1840.22 748.83,1841.52 cw(c757.52,1850.21) 745.23,1850.21 745.23,1851.36 cw(c752.64,1851.36) 747.4,1856.59 cw(c749.94,1854.05) 749.94,1857.65 ccw(c749.94,1861.24) 752.48,1858.69 754.06,1860.27 ccw(c747.72,1866.61) 756.68,1866.61 P5.64@756.68,1899.4
  Int2 (Sign) w3: v1(157.48,275.59) 165.29,275.59 cw(c165.29,267.72) 173.17,267.72 cw(c165.29,267.72) 165.29,259.84 157.48,259.84 cw(c157.48,275.59) 141.73,275.59 cw(c157.48,275.59) 157.48,291.34 157.61,291.34 ccw(c157.61,314.96) 181.23,314.96 181.23,935.58 cw(c281.23,935.58) 210.52,1006.29 692.81,1488.58 ccw(c616.51,1564.88) 724.41,1564.88 724.41,1758.58 cw(c757.17,1758.58) 734,1781.74 734.75,1782.49 ccw(c710.16,1807.08) 744.93,1807.08 744.93,1816.54 cw(c763.88,1816.54) 750.48,1829.94 ccw(c745.77,1834.65) v2(752.43,1834.65)
S49_64.S63_N: P5.68 U16.U21 | length 1783.7
  Top Layer w5: U16.U21@216.54,374.02 v1(236.22,393.7) ; v2(815.43,1834.65) ccw(c807.53,1834.65) 813.13,1840.22 811.83,1841.52 cw(c820.52,1850.21) 808.23,1850.21 808.23,1851.36 cw(c815.64,1851.36) 810.4,1856.59 cw(c812.94,1854.05) 812.94,1857.65 ccw(c812.94,1861.24) 815.48,1858.69 817.06,1860.27 ccw(c810.72,1866.61) 819.68,1866.61 P5.68@819.68,1899.4
  Int2 (Sign) w3: v1(236.22,393.7) cw(c236.22,409.39) 220.54,409.39 220.54,915.83 cw(c320.54,915.83) 249.76,986.48 cw(c320.54,915.83) 249.83,986.54 724.43,1461.15 ccw(c648.13,1537.44) 756.03,1537.44 756.03,1732.28 cw(c778.48,1732.28) 762.6,1748.15 795.58,1781.13 ccw(c765.76,1810.95) 807.93,1810.95 807.93,1816.54 cw(c826.88,1816.54) 813.48,1829.94 ccw(c808.77,1834.65) v2(815.43,1834.65)
S49_64.S63_P: P5.66 U16.T21 | length 1783.7
  Top Layer w5: U16.T21@177.17,374.02 v1(196.85,393.7) ; P5.66@788.18,1899.4 788.18,1866.61 ccw(c797.14,1866.61) 790.8,1860.28 792.38,1858.7 ccw(c794.92,1861.24) 794.92,1857.65 cw(c794.92,1854.05) 797.46,1856.59 cw(c792.23,1851.36) 799.63,1851.36 799.63,1850.21 cw(c787.34,1850.21) 796.03,1841.52 794.75,1840.23 ccw(c800.33,1834.65) v2(792.43,1834.65)
  Int2 (Sign) w3: v1(196.85,393.7) ccw(c196.85,409.39) 212.54,409.39 212.54,916.47 cw(c319,916.47) 243.72,991.75 718.74,1466.77 ccw(c648.03,1537.48) 748.03,1537.48 748.03,1732.32 cw(c778.39,1732.32) 756.92,1753.79 789.87,1786.74 ccw(c765.59,1811.02) 799.93,1811.02 799.93,1816.54 ccw(c780.98,1816.54) 794.38,1829.94 cw(c799.09,1834.65) v2(792.43,1834.65)
S49_64.S64_N: P5.70 U16.V19 | length 2418
  Top Layer w5: U16.V19@255.91,295.28 v1(275.59,314.96) ; P5.70@851.16,1899.4 851.16,1866.61 ccw(c860.13,1866.61) 853.78,1860.28 855.36,1858.7 ccw(c857.9,1861.24) 857.9,1857.65 cw(c857.9,1854.05) 860.45,1856.59 cw(c855.21,1851.36) 862.61,1851.36 862.61,1850.21 cw(c850.32,1850.21) 859.01,1841.52 857.73,1840.23 ccw(c863.31,1834.65) v2(855.41,1834.65)
  Int6 (Sign) w3: v1(275.59,314.96) 275.59,307.15 ccw(c283.46,307.15) 283.46,299.28 ccw(c283.46,307.15) 291.34,307.15 291.34,499.59 cw(c823.39,499.59) 291.66,517.96 291.66,1329.14 cw(c399.56,1329.14) 323.26,1405.44 560.06,1642.24 cw(c636.35,1565.94) 636.35,1673.84 1017.84,1673.84 ccw(c1017.84,1734.74) 1078.74,1734.74 ccw(c1015.21,1734.74) 1015.21,1798.28 883.77,1798.28 cw(c883.77,1818.9) 863.15,1818.9 ccw(c850.48,1818.9) 859.44,1827.86 857.36,1829.95 cw(c862.07,1834.65) v2(855.41,1834.65)
S49_64.S64_P: P5.72 U16.V18 | length 2430.3
  Top Layer w5: U16.V18@255.91,255.91 v1(275.59,275.59) ; v2(878.41,1834.65) ccw(c870.52,1834.65) 876.11,1840.22 874.81,1841.52 cw(c883.51,1850.21) 871.21,1850.21 871.21,1851.36 cw(c878.62,1851.36) 873.38,1856.59 cw(c875.93,1854.05) 875.93,1857.65 ccw(c875.93,1861.24) 878.46,1858.69 880.04,1860.27 ccw(c873.7,1866.61) 882.66,1866.61 P5.72@882.66,1899.4
  Int6 (Sign) w3: v1(275.59,275.59) 275.59,283.4 cw(c283.46,283.4) 283.46,291.28 ccw(c283.46,307.15) 299.34,307.15 299.34,499.55 cw(c823.49,499.55) 299.66,517.96 299.66,1329.1 cw(c399.66,1329.1) 328.95,1399.81 565.68,1636.55 cw(c636.39,1565.84) 636.39,1665.84 1017.84,1665.84 ccw(c1017.84,1734.74) 1086.74,1734.74 ccw(c1015.21,1734.74) 1015.21,1806.28 883.77,1806.28 cw(c883.77,1818.9) 871.15,1818.9 cw(c884.41,1818.9) 875.03,1828.26 876.3,1829.53 ccw(c871.18,1834.65) v2(878.41,1834.65)
SCL: J2.5 R112.1 | length 112.2
  Top Layer w10: J2.5@2271.65,1687.8 v1(2342.52,1687.8)
  Bottom Layer w10: R112.1@2301.18,1687.8 v1(2342.52,1687.8)
SCLK: U11.8 U12.8 U14.14 | length 970.8
  Top Layer w10: U11.8@-1409.45,-1515.75 -1429.13,-1515.75 -1434.51,-1510.37 -1434.51,-1500 ccw(c-1495.01,-1500) -1452.2,-1457.25 -1453.47,-1455.97 cw(c-1407.69,-1410.19) -1472.44,-1410.19 -1472.44,-1142.72 ; U12.8@-1409.45,-1142.72 -1472.44,-1142.72 ; U14.14@-1290.35,-747.05 -1323.82,-747.05 ccw(c-1323.82,-827.84) -1380.93,-770.7 -1443.15,-832.92 ccw(c-1372.44,-903.63) -1472.44,-903.63 -1472.44,-1142.72
SDA: J2.4 R111.1 | length 112.2
  Top Layer w10: J2.4@2271.65,1656.3 v1(2342.52,1656.3)
  Bottom Layer w10: R111.1@2301.18,1656.3 v1(2342.52,1656.3)
SENS1: R5.2 U2.19 | length 237.5
  Top Layer w10: R5.2@-2212.6,-299.21 -2170.46,-257.08 cw(c-2148.62,-278.92) -2148.62,-248.03 -2110.5,-248.03 ccw(c-2110.5,-209.39) -2083.2,-236.74 ; -2083.14,-236.69 ccw(c-2110.5,-209.39) -2071.85,-209.39 U2.19@-2071.85,-154.53
SENS2: R6.2 U2.20 | length 143.6
  Top Layer w10: R6.2@-2053.15,-295.28 -2046.26,-288.39 U2.20@-2046.26,-154.53
SENS3: R10.2 U2.21 | length 162.3
  Top Layer w10: U2.21@-2020.67,-154.53 -2020.67,-222.99 ccw(c-1981.6,-222.99) -2009.23,-250.62 R10.2@-1964.57,-295.28
SENS4: R12.2 U2.22 | length 275.2
  Top Layer w10: U2.22@-1995.08,-154.53 -1994.96,-154.64 -1994.96,-194.88 ccw(c-1959.05,-194.88) -1984.44,-220.28 -1981.73,-222.99 ccw(c-1949.79,-191.05) -1949.79,-236.22 -1893.45,-236.22 cw(c-1893.45,-306.9) -1843.49,-256.9 ; -1843.47,-256.92 -1821.77,-278.62 -1821.77,-280.59 -1807.09,-295.28 R12.2@-1805.12,-295.28
SENS5: R190.2 R191.1 U2.23 | length 256.4
  Top Layer w10: v3(-2066.93,-59.06) -2043.31,-82.68 -1992.13,-82.68 -1969.49,-105.31 U2.23@-1969.49,-154.53
  Bottom Layer w10: R190.2@-2066.93,-104.33 R191.1@-2066.93,-13.78
SENS6: R187.2 R188.1 U2.24 | length 228.7
  Top Layer w10: v3(-2007.87,-59.06) -1980.31,-59.06 -1943.9,-95.47 U2.24@-1943.9,-154.53
  Bottom Layer w10: R187.2@-2007.87,-104.33 R188.1@-2007.87,-13.78
SENS7: R182.2 R183.1 U2.25 | length 198.7
  Top Layer w10: v3(-1948.82,-59.06) -1918.31,-89.57 U2.25@-1918.31,-154.53
  Bottom Layer w10: R182.2@-1948.82,-104.33 R183.1@-1948.82,-13.78
SENS8: R176.2 R177.1 U2.26 | length 196.3
  Top Layer w10: U2.26@-1892.72,-154.53 v3(-1892.72,-59.06)
  Bottom Layer w10: R176.2@-1889.76,-104.33 -1892.72,-101.38 -1892.72,-8.86 R177.1@-1889.76,-5.91
SENS9: R193.2 R201.1 U2.11 | length 1425.3
  Top Layer w10: U2.11@-2097.44,75.79 v3(-2097.44,129.43)
  Int2 (Sign) w10: v3(-2342.52,-59.06) v3(-2097.44,129.43)
  Bottom Layer w10: -2460.66,-177.2 ccw(c-2413.11,-224.69) -2480.32,-224.69 -2480.32,-295.28 -2480.31,-587.17 ccw(c-2413.11,-587.17) -2460.63,-634.7 -2415.1,-680.23 ; -2460.63,-177.17 -2314.43,-30.96 -2314.43,-21.12 -2303.15,-9.84 R201.1@-2303.15,-5.91 ; -2415.07,-680.25 ccw(c-2346.46,-611.59) -2346.46,-708.66 -2252.05,-708.66 cw(c-2252.05,-808.66) -2181.34,-737.95 -2164.29,-755 -2164.29,-758.94 -2155.51,-767.72 R193.2@-2151.57,-767.72
SENS10: R181.2 R199.1 U2.10 | length 1550
  Top Layer w10: U2.10@-2071.85,75.79 v3(-2071.85,129.43)
  Int2 (Sign) w10: v3(-2283.46,-59.06) v3(-2071.85,129.43)
  Bottom Layer w10: -2442.93,-624.56 cw(c-2400.16,-581.81) -2460.63,-581.81 -2460.63,-264.06 cw(c-2393.42,-264.06) -2440.94,-216.54 -2303.15,-78.74 -2255.37,-30.96 -2255.37,-21.12 -2244.09,-9.84 R199.1@-2244.09,-5.91 ; -2442.92,-624.57 -2401.57,-665.92 ccw(c-2345.9,-610.24) -2345.9,-688.98 -2114.26,-688.98 cw(c-2114.26,-788.98) -2043.55,-718.27 -2006.81,-755 -2006.81,-758.94 -1998.03,-767.72 R181.2@-1994.09,-767.72
SENS11: R169.2 R196.1 U2.9 | length 1663.6
  Top Layer w10: U2.9@-2046.26,75.79 v3(-2046.26,129.43)
  Int2 (Sign) w10: v3(-2224.41,-59.06) v3(-2046.26,129.43)
  Bottom Layer w10: R196.1@-2185.04,-5.91 -2185.04,-9.84 -2196.32,-21.12 -2196.32,-30.96 -2415.84,-250.49 ccw(c-2355.24,-311.09) -2440.94,-311.09 -2440.94,-563.2 ccw(c-2355.24,-563.2) -2415.84,-623.81 -2390.74,-648.91 ccw(c-2341.54,-599.71) -2341.54,-669.29 -1986.3,-669.29 cw(c-1986.3,-769.29) -1915.59,-698.58 -1846.46,-767.72 R169.2@-1844.49,-767.72
SENS12: R160.2 R194.1 U2.8 | length 1795.5
  Top Layer w10: U2.8@-2020.67,75.79 v3(-2020.67,129.43)
  Int2 (Sign) w10: v3(-2165.35,-59.06) v3(-2020.67,129.43)
  Bottom Layer w10: -2387.24,-624.57 ccw(c-2326.77,-564.06) -2326.77,-649.61 -1838.67,-649.61 cw(c-1838.67,-749.61) -1767.95,-678.9 -1691.85,-755 -1691.85,-758.94 -1683.07,-767.72 R160.2@-1679.13,-767.72 ; -2387.26,-624.55 -2400.38,-611.43 cw(c-2349.97,-561.02) -2421.26,-561.02 -2421.26,-352.36 cw(c-2330.96,-352.36) -2394.81,-288.51 -2224.41,-118.11 -2137.26,-30.96 -2137.26,-21.12 -2129.92,-13.78 R194.1@-2125.98,-13.78
SENS13: R171.2 R172.1 U2.7 | length 394.3
  Top Layer w10: U2.7@-1995.08,75.79 v3(-1995.08,129.43)
  Int2 (Sign) w10: v3(-1995.08,129.43) v3(-1830.71,-59.06)
  Bottom Layer w10: R171.2@-1830.71,-104.33 R172.1@-1830.71,-13.78
SENS14: R130.2 R167.1 U2.6 | length 3508.7
  Top Layer w10: U2.6@-1969.49,75.79 v3(-1969.49,129.43)
  Int6 (Sign) w10: v3(-1771.65,-59.06) cw(c-1724.13,-106.58) -1724.13,-39.37 -1616.22,-39.37 cw(c-1616.22,-139.37) -1545.58,-68.6 cw(c-1616.22,-139.37) -1545.51,-68.66 ; -1551.18,-62.99 -1545.04,-69.14 ccw(c-1474.33,1.57) -1474.33,-98.43 -536.42,-98.43 536.42,-98.43 1108.18,-98.43 ccw(c1108.18,1.57) 1178.9,-69.14 v2(1220.47,-27.56)
  Int2 (Sign) w10: v3(-1969.49,129.43) v3(-1771.65,-59.06)
  Bottom Layer w10: v3(-1771.65,-59.06) R167.1@-1771.65,-13.78 ; v2(1220.47,-27.56) 1305.12,-27.56 R130.2@1309.06,-23.62
SENS15: R142.2 R163.1 U2.5 | length 2711.2
  Top Layer w10: U2.5@-1943.9,75.79 v3(-1943.9,129.43)
  Int2 (Sign) w10: v3(-1943.9,129.43) v3(-1712.6,-59.06)
  Int7 (Sign) w10: v3(-1712.6,-59.06) -1712.6,-293.22 ccw(c-1612.6,-293.22) -1683.31,-363.93 -1426.93,-620.32 ccw(c-1356.22,-549.61) -1356.22,-649.61 -1320.95,-649.61 cw(c-1320.95,-749.61) -1250.24,-678.9 -1210.39,-718.74 cw(c-1281.1,-789.45) -1181.1,-789.45 -1181.1,-824.72 ccw(c-1081.1,-824.72) -1151.81,-895.43 -797.01,-1250.24 ccw(c-726.3,-1179.53) -726.3,-1279.53 -574.89,-1279.53 cw(c-574.89,-1379.53) -504.18,-1308.82 v6(-230.32,-1582.68)
  Bottom Layer w10: v3(-1712.6,-59.06) R163.1@-1712.6,-13.78
SENS16: Q2.3 Q3.3 R45.1 U2.4 | length 3623.5
  Top Layer w10: U2.4@-1918.31,75.79 v3(-1918.31,129.43) ; v2(1122.05,-161.42) Q2.3@1122.05,-196.85 R45.1@1476.38,-196.85
  Int6 (Sign) w10: v3(-1653.54,-59.06) -1525.35,-187.25 ccw(c-1454.64,-116.54) -1454.64,-216.54 -536.42,-216.54 536.42,-216.54 1025.51,-216.54 ccw(c1025.51,-116.54) 1096.22,-187.25 v2(1122.05,-161.42)
  Int2 (Sign) w10: v3(-1918.31,129.43) v3(-1653.54,-59.06)
SENSE.SENS_10_P: C69.1 L4.2 R77.2 R96.1 U5.3 | length 6351.6
  Top Layer w10: v3(-2073.82,-618.11) U5.3@-2073.82,-579.72 ; R77.2@2185.03,-1486.21 2192.91,-1494.09 2192.91,-1557.09 2208.66,-1572.83 2620.07,-1572.83 2639.35,-1553.55 2661.49,-1553.55 2670.13,-1544.92 R96.1@2670.13,-1522.78
  Int6 (Sign) w9.5: -2002.94,-1350.39 -1989.18,-1350.39
  Int6 (Sign) w10: v3(-2073.82,-618.11) -2073.82,-619.73 -2078.74,-624.66 -2078.74,-698.72 -2168.79,-788.77 -2168.79,-991.92 -2110.74,-1049.96 -2110.74,-1242.88 -2003.22,-1350.39 -2002.94,-1350.39 ; -1989.18,-1350.39 -1379.83,-1350.39 -1311.29,-1281.86 -975.49,-1281.86 -914.6,-1220.98 -631.14,-1220.98 -564.21,-1154.05 1086.41,-1154.05 1420.04,-1487.68 2388.55,-1487.68 2479.1,-1578.24 2610.2,-1578.24 2617.57,-1570.87 v4(2618.11,-1570.87)
SENSE.SENS_18_P: C46.2 L3.2 R48.1 R68.2 U6.3 | length 5110
  Top Layer w10: v3(-1916.34,-618.09) U6.3@-1916.34,-579.72 ; v4(1543.31,-838.58) 1543.85,-838.58 1544.85,-837.58 1546.28,-837.58 1565.66,-818.2 1587.31,-818.2 R48.1@1610.24,-795.28 1634.46,-819.5 1654.15,-819.5 1711.5,-876.85 1711.5,-918.39 1725.79,-932.68 L3.2@1768.58,-932.68 ; L3.2@1809.98,-926.11 1889.76,-926.11 1894.68,-931.03 1910.91,-914.8 1910.91,-872 1916.78,-866.13 R68.2@2031.49,-866.13
  Int6 (Sign) w10: v3(-1916.34,-618.09) -1916.34,-619.71 -1919.34,-622.71 -1919.34,-623.26 -1921.26,-625.18 -1921.26,-687.63 -2019.69,-786.05 -2019.69,-1194.26 -1961.98,-1251.97 -1602.36,-1251.97 -1330.71,-980.31 -582.68,-980.31 -468.5,-1094.49 1095.74,-1094.49 1347.71,-842.52 1537.96,-842.52 1540.89,-839.58 1541.77,-839.58 1542.77,-838.58 v4(1543.31,-838.58)
SENSE.SENS_25_P: C70.2 L5.2 R78.2 R97.1 U8.3 | length 6514.7
  Top Layer w10: v3(-1758.86,-618.09) U8.3@-1758.86,-579.72 ; R78.2@2181.1,-866.13 2189.72,-857.52 2594.73,-857.52 2647.35,-910.14 2661.49,-910.14 2676.96,-925.6 2676.96,-939.74 2687.01,-949.79 C70.2@2687.01,-1037.39
  Int6 (Sign) w10: v3(-1758.86,-618.09) -1758.86,-619.71 -1764.5,-625.36 -1764.5,-857.97 -1959.91,-1053.38 -1959.91,-1168.99 -1936.71,-1192.19 -1600.62,-1192.19 -1318.6,-910.17 -556.77,-910.17 -510.97,-955.97 -435.27,-955.97 -405.21,-925.92 696.46,-925.92 905.12,-717.26 1583.07,-717.26 1841.47,-975.66 2676.87,-975.66 2707.94,-944.58 2707.94,-884.77 2674.28,-851.12 2625.8,-851.12 2618.65,-858.27 v4(2618.11,-858.27)
SENSE.SENS_33_P: C45.2 L2.2 R49.1 R67.2 U1.3 | length 5473.1
  Top Layer w10: v3(-2231.3,-618.09) U1.3@-2231.3,-579.72 ; L2.2@1741.6,-1506.28 1741.6,-1505.28 1756.72,-1490.16 1815.39,-1490.16 1830.51,-1505.28 1847.8,-1505.28 1915.35,-1572.83 2003.94,-1572.83 2019.68,-1557.09 2019.68,-1496.97 2030.44,-1486.21 R67.2@2031.49,-1486.21 ; L2.2@1809.98,-1481.35 1883.79,-1481.35 C45.2@1889.76,-1475.38
  Int6 (Sign) w10: v3(-2231.3,-618.09) -2231.3,-619.71 -2234.3,-622.71 -2234.3,-623.26 -2236.22,-625.18 -2236.22,-691.56 -2295.28,-750.62 -2295.28,-1216.54 -1933.07,-1578.74 -1419.91,-1578.74 -1270.3,-1429.13 -1031.5,-1429.13 -885.83,-1283.46 -594.49,-1283.46 -523.62,-1212.6 1066.93,-1212.6 1429.13,-1574.8 1565.85,-1574.8 1572.72,-1567.93 1573.26,-1567.93 1574.26,-1566.93 v4(1574.8,-1566.93)
SENSE.SENS_120b_P: D2.2 R140.1 R143.1
SENSE.SENS_120x_P: C74.1 D1.2 R46.2 R99.1 | length 1814.8
  Top Layer w10: R46.2@1568.9,-456.69 1570.87,-456.69 1585.55,-442.01 1585.55,-440.04 1587.19,-438.4 cw(c1628.57,-479.78) 1628.57,-421.26 1637.09,-421.26 cw(c1637.09,-521.26) 1707.81,-450.55 1821.78,-564.52 ccw(c1903.63,-482.68) 1903.63,-598.43 2385.13,-598.43 ccw(c2385.13,-482.68) 2466.97,-564.52 2632.13,-399.37 cw(c2702.84,-470.08) 2702.84,-370.08 2832.68,-370.08 cw(c2832.68,-388.23) 2850.83,-388.23 2857,-394.4 2878.65,-394.4 R99.1@2901.57,-417.32 2905.51,-417.32 2932.01,-443.82 2932.01,-448.02 2933.66,-449.68 2933.66,-552.76 D1.2@2952.76,-571.85 ; R99.1@2914.21,-404.69 3027.4,-404.69 C74.1@3031.5,-400.59
SFP_SH: C76.1 J2.21 J2.22 R107.1 | length 158.6
  Bottom Layer w10: R107.1@3246.06,1673.23 3246.97,1674.13 3246.97,1687.79 3247.05,1687.87 3247.05,1750.98 3248.82,1752.76 J2.21@3326.77,1752.76
SFPIN.LEDIN: Q5.1 U16.V17 | length 4047.1
  Top Layer w10: U16.V17@255.91,216.54 v1(275.59,236.22)
  Bottom Layer w10: v1(275.59,236.22) ccw(c295.28,236.22) 295.28,216.54 314.96,216.54 ccw(c314.96,236.22) 334.65,236.22 334.65,275.59 cw(c354.33,275.59) 354.33,295.28 452.76,295.28 655.43,295.28 ccw(c655.43,395.28) 726.14,324.56 1624.25,1222.68 cw(c1694.96,1151.97) 1694.96,1251.97 2482.2,1251.97 ccw(c2482.2,1351.97) 2552.91,1281.26 3134.1,1862.44 cw(c3204.81,1791.73) 3204.81,1891.73 Q5.1@3577.76,1891.73
SFPIN.LOS: J2.8 R114.1 U16.W17 | length 3182.7
  Top Layer w10: U16.W17@295.28,216.54 v1(314.96,236.22) ; J2.8@2271.65,1782.28 v1(2342.52,1782.28)
  Bottom Layer w10: v1(314.96,236.22) cw(c314.96,255.91) 295.28,255.91 295.28,314.96 cw(c314.96,314.96) 314.96,334.65 452.76,334.65 627.87,334.65 ccw(c627.87,434.65) 698.58,363.94 1624.25,1289.61 cw(c1694.96,1218.9) 1694.96,1318.9 2281.89,1318.9 ccw(c2281.89,1418.9) 2381.89,1418.9 2381.89,1701.49 ccw(c2281.89,1701.49) 2352.6,1772.2 2333.38,1791.42 ccw(c2306.63,1764.67) 2306.63,1802.5 2304.59,1802.5 2293.31,1813.78 R114.1@2289.37,1813.78
SFPIN.SYNCIN_N: U16.R17 U32.7 | length 2622.2
  Top Layer w5: U16.R17@137.8,216.54 v1(157.48,236.22)
  Bottom Layer w5: v1(157.48,236.22) cw(c157.48,251.72) 141.98,251.72 141.68,252.02 141.68,452.76 141.68,690.81 141.98,691.11 cw(c241.98,691.11) 171.27,761.82 1068.41,1658.96 cw(c1139.12,1588.25) 1139.12,1688.25 1653.54,1688.25 ccw(c1653.54,1724.41) 1689.7,1724.41 1689.7,1751.61 ccw(c1653.54,1751.61) 1653.54,1787.76 1644.23,1787.76 cw(c1644.23,1802.27) 1633.97,1792.01 ccw(c1623.72,1781.76) 1623.72,1796.26 U32.7@1606.5,1796.26
SFPIN.SYNCIN_P: U16.P16 U32.6 | length 2647.9
  Top Layer w5: U16.P16@98.43,177.17 v1(118.11,196.85)
  Bottom Layer w5: v1(118.11,196.85) ccw(c118.11,212.12) 133.38,212.12 133.38,251.72 133.68,252.02 133.68,452.76 133.68,687.77 133.38,688.07 133.38,691.23 cw(c241.69,691.23) 165.11,767.82 1062.41,1665.13 cw(c1139,1588.54) 1139,1696.85 1653.54,1696.85 ccw(c1653.54,1724.41) 1681.1,1724.41 1681.1,1751.61 ccw(c1653.54,1751.61) 1653.54,1779.16 1644.23,1779.16 ccw(c1644.23,1764.66) 1633.97,1774.92 cw(c1623.72,1785.17) 1623.72,1770.67 U32.6@1606.5,1770.67
SFPIN.SYNCOUT_N: U16.W22 U33.2 | length 2107.1
  Top Layer w5: U16.W22@295.28,413.39 v1(314.96,433.07)
  Bottom Layer w5: v1(314.96,433.07) ccw(c321.2,426.84) 312.38,426.84 312.38,424.28 cw(c305.79,424.28) 310.45,419.62 cw(c305.79,424.28) 305.79,417.69 275.23,417.69 cw(c275.23,452.76) 240.16,452.76 240.16,655.43 cw(c340.16,655.43) 269.45,726.14 1104.21,1560.9 cw(c1174.92,1490.19) 1174.92,1590.19 1568.37,1590.19 cw(c1568.37,1575.69) 1578.63,1585.94 ccw(c1588.88,1596.2) 1588.88,1581.69 U33.2@1606.1,1581.69
SFPIN.SYNCOUT_P: U16.W21 U33.3 | length 2134.1
  Top Layer w5: U16.W21@295.28,374.02 v1(314.96,393.7)
  Bottom Layer w5: v1(314.96,393.7) cw(c321.2,399.94) 312.38,399.94 312.38,402.5 ccw(c305.79,402.5) 310.45,407.16 ccw(c305.79,402.5) 305.79,409.09 275.23,409.09 cw(c275.23,452.76) 231.56,452.76 231.56,655.55 cw(c339.87,655.55) 263.28,732.14 1098.21,1567.06 cw(c1174.8,1490.48) 1174.8,1598.79 1568.37,1598.79 ccw(c1568.37,1613.29) 1578.63,1603.04 cw(c1588.88,1592.78) 1588.88,1607.28 U33.3@1606.1,1607.28
SMCLK: P3.B5
SMDAT: P3.B6
SQSPI.EMCLK_EN: R38.2 U16.U7 Y1.1 | length 1380.5
  Top Layer w10: U16.U7@216.54,-177.17 v1(236.22,-196.85) ; Y1.1@996.06,704.72 1000,708.66 v1(1082.68,708.66)
  Int3 (Sign) w8.59: 255.91,-139.85 cw(c355.91,-139.85) 285.19,-69.14
  Int3 (Sign) w10: v1(236.22,-196.85) ccw(c236.22,-177.17) 255.91,-177.17 255.91,-139.85 ; 285.19,-69.14 536.42,182.09 1049.07,694.74 cw(c1082.68,661.14) v1(1082.68,708.66)
SQSPI.PUDC_B: R28.1 R29.1 U16.U22 | length 118
  Top Layer w10: R28.1@200.79,478.35 205.63,473.5 216.54,462.6 ; U16.U22@216.54,413.39 216.54,452.76 216.54,462.6 ; R29.1@255.91,478.35 255.91,477.28 241.22,462.6 216.54,462.6
SQSPI.QSPI_CS: R42.2 U16.T19 U18.7 U20.1 | length 1871.5
  Top Layer w10: U16.T19@177.17,295.28 v1(196.85,314.96) ; U20.1@1177.36,1273.23 1177.36,1266.91 1180.02,1264.25 1180.56,1264.25 1217.45,1227.36 R42.2@1368.89,1227.36 1368.89,1199.73 ccw(c1372.96,1199.73) v1@1370.08,1196.85
  Bottom Layer w10: v1(196.85,314.96) cw(c216.54,314.96) 216.54,334.65 236.22,334.65 ccw(c236.22,354.33) 255.91,354.33 cw(c275.59,354.33) 275.59,374.02 452.76,374.02 608.18,374.02 ccw(c608.18,474.02) 678.9,403.31 1339.6,1064.01 ccw(c1268.89,1134.72) 1368.89,1134.72 v1(1368.89,1196.85)
SQSPI.QSPI_DQ0: R35.2 U16.P22 | length 1180.7
  Top Layer w10: U16.P22@98.43,413.39 98.43,452.76 98.43,686.93 cw(c198.43,686.93) 127.71,757.64 403.78,1033.7 cw(c474.49,962.99) 474.49,1062.99 777.77,1062.99 ccw(c777.77,1107.98) 809.59,1076.17 809.59,1077.3 822.83,1090.55 R35.2@823.97,1090.55
SQSPI.QSPI_DQ1: R31.2 U16.R22 | length 970.3
  Top Layer w10: U16.R22@137.8,413.39 137.8,452.76 137.8,568.81 cw(c237.8,568.81) 167.08,639.53 478.58,951.03 cw(c549.3,880.32) 549.3,980.32 667.78,980.32 ccw(c667.78,1060.01) 724.09,1003.62 ; 724.13,1003.66 730.65,1010.18 731.33,1010.18 748.52,1027.36 R31.2@748.52,1029.33
SQSPI.QSPI_DQ2: R30.2 U16.P21 | length 993.6
  Top Layer w10: U16.P21@98.43,374.02 ccw(c98.43,393.7) 118.11,393.7 118.11,452.76 118.11,627.87 cw(c218.11,627.87) 147.4,698.58 440.65,991.83 cw(c511.36,921.12) 511.36,1021.12 667.83,1021.12 R30.2@667.99,1021.28
SQSPI.QSPI_DQ3: R39.2 U16.R21 | length 1236.4
  Top Layer w8.41: 332.89,726.59 344.27,737.97
  Top Layer w10: U16.R21@137.8,374.02 ccw(c137.8,393.7) 157.48,393.7 157.48,452.76 157.48,509.76 cw(c257.48,509.76) 186.77,580.47 332.89,726.59 ; 344.27,737.97 397.88,791.58 cw(c468.59,720.87) 468.59,820.87 R39.2@1102.36,820.87
SQSPI.QSPI_EMCLK: U16.V22 Y1.3 | length 765
  Top Layer w10: U16.V22@255.91,413.39 295.28,452.76 452.14,609.62 cw(c522.85,538.91) 522.85,638.91 Y1.3@931.79,638.91
SQSPI.XMUX0: U15.13 U16.F21 | length 1117
  Top Layer w10: U15.13@-1071.85,12.79 v3(-1003.94,12.79) ; v1(-236.22,393.7) U16.F21@-216.54,374.02
  Int6 (Sign) w10: v3(-1003.94,12.79) -1003.94,37.8 cw(c-785.83,37.8) -785.83,255.91 -536.42,255.91 -393.7,255.91 ccw(c-393.7,275.59) -374.02,275.59 -374.02,314.96 cw(c-354.33,314.96) -354.33,334.65 -275.59,334.65 ccw(c-275.59,354.33) -255.91,354.33 -255.91,374.02 cw(c-236.22,374.02) v1(-236.22,393.7)
SQSPI.XMUX1: U15.12 U16.M17 | length 1302.9
  Top Layer w10: U15.12@-1071.85,-12.8 v3(-984.25,-12.8) ; U16.M17@19.69,216.54 v1(39.37,236.22)
  Int6 (Sign) w10: v3(-984.25,-12.8) -984.25,37.8 cw(c-805.51,37.8) -805.51,216.54 -536.42,216.54 19.68,216.54 ccw(c19.68,236.22) v1(39.37,236.22)
SQSPI.XMUX2: U15.11 U16.J16 | length 1148.5
  Top Layer w10: U15.11@-1071.85,-38.39 v3(-964.57,-38.39) ; v1(-118.11,196.85) U16.J16@-98.43,177.17
  Int6 (Sign) w10: v3(-964.57,-38.39) -964.57,37.8 cw(c-825.2,37.8) -825.2,177.17 -536.42,177.17 -137.8,177.17 ccw(c-137.8,196.85) v1(-118.11,196.85)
